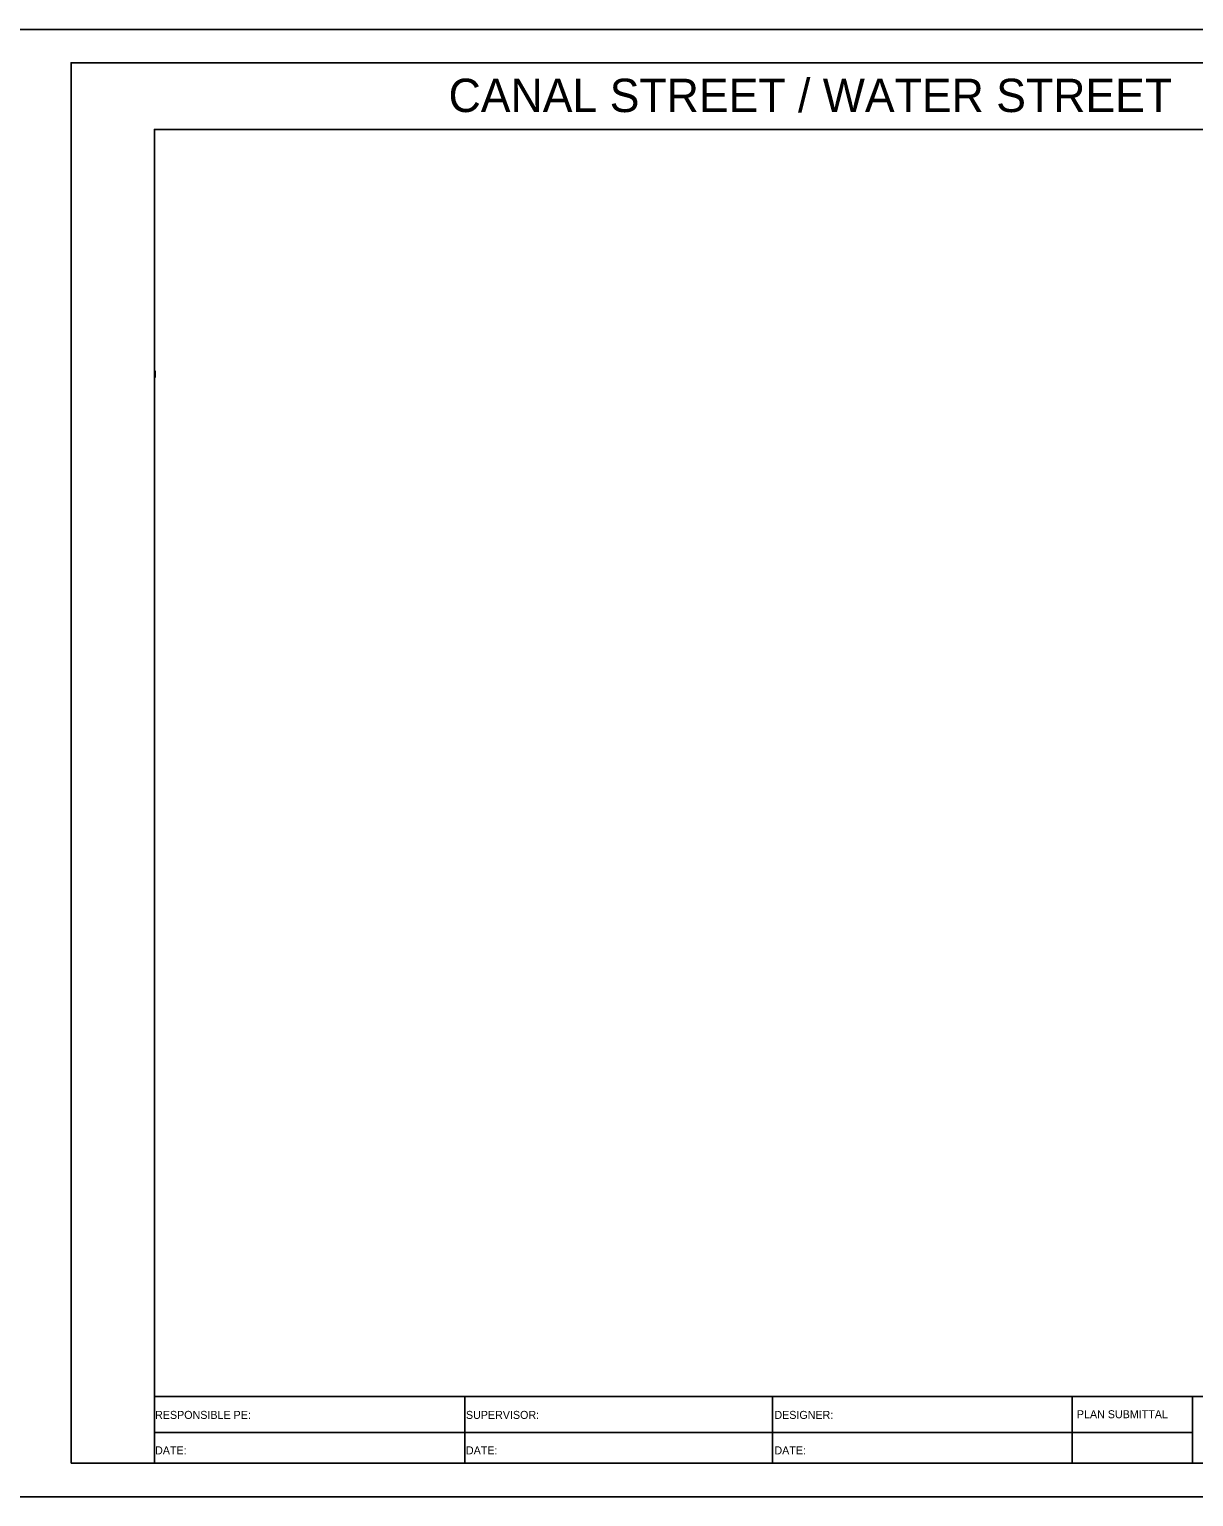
# Model space of a CAD drawing. Extents: x 1797478 to 1808916, y 246529 to 250952.
# Drawn here: x 1802802.3 to 1802976.8, y 250064.4 to 250284.4 of the extents above; entities that cross this region are included whole.
import ezdxf

# ---------------------------------------------------------------- set-up
doc = ezdxf.new("R2010")
doc.units = 0
for name, color, linetype in [('2', 7, 'Continuous'), ('ANNO-SHT', 7, 'Continuous'), ('ANNO-TXT', 7, 'Continuous'), ('AXIS', 7, 'Continuous'), ('DRAINAGE', 7, 'Continuous'), ('Level 1', 7, 'Continuous'), ('Level 62', 7, 'Continuous'), ('SHT-BDR', 7, 'Continuous'), ('SHT-BNDRY', 7, 'Continuous')]:
    doc.layers.add(name, color=color, linetype=linetype)

# ---------------------------------------------------------------- blocks, each defined once
blk = doc.blocks.new('SC47208')
at = {"layer": 'Level 1'}
blk.add_line((0, 0), (0, 0), dxfattribs=at)

msp = doc.modelspace()

# ---------------------------------------------------------------- linework, layer by layer
at = {"layer": '2'}
msp.add_lwpolyline([(1802821.12, 250233.21), (1802821.1, 250232.21)], dxfattribs=at)
msp.add_lwpolyline([(1802821.12, 250233.21), (1802821.1, 250232.21)], dxfattribs=at)
at = {"layer": 'AXIS'}
msp.add_line((1802821, 250189.42), (1802821, 250189.43), dxfattribs=at)
at = {"layer": 'Level 62'}
msp.add_lwpolyline([(1802796, 250064.42), (1803136, 250064.42), (1803136, 250284.42), (1802796, 250284.42)], close=True, dxfattribs=at)
at = {"layer": 'SHT-BDR'}
msp.add_lwpolyline([(1802821, 250079.43), (1803121, 250079.43), (1803121, 250269.43), (1802821, 250269.43)], close=True, dxfattribs=at)
at = {"layer": 'SHT-BNDRY'}
for p, q in [((1802821, 250069.42), (1802821, 250079.43)), ((1802867.52, 250079.43), (1802867.52, 250069.42)), ((1802913.67, 250069.42), (1802913.67, 250079.43)), ((1802958.59, 250069.42), (1802958.59, 250079.43)), ((1802976.63, 250069.42), (1802976.63, 250079.43)), ((1802821, 250074.03), (1802976.63, 250074.03))]:
    msp.add_line(p, q, dxfattribs=at)
msp.add_lwpolyline([(1802808.5, 250069.42), (1803131, 250069.42), (1803131, 250279.42), (1802808.5, 250279.42)], close=True, dxfattribs=at)

# ---------------------------------------------------------------- block references
at = {"layer": 'DRAINAGE', "xscale": 0.2, "yscale": 0.20000000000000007, "rotation": -116.41666666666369}
msp.add_blockref('SC47208', (1802971.32, 250274.62), dxfattribs=at)
msp.add_blockref('SC47208', (1802971.32, 250274.62), dxfattribs=at)

# ---------------------------------------------------------------- texts
at = {"layer": 'ANNO-SHT'}
msp.add_text('         CANAL STREET / WATER STREET         ', height=4.9995, rotation=360, dxfattribs=at).set_placement((1802848.38, 250272.02))
at = {"layer": 'ANNO-TXT'}
for s, p in [('RESPONSIBLE PE:', (1802821.1, 250076.08)), ('SUPERVISOR:', (1802867.7, 250076.08)), ('DESIGNER:', (1802913.94, 250076.08)), ('PLAN SUBMITTAL', (1802959.28, 250076.18)), ('DATE:', (1802821.1, 250070.76)), ('DATE:', (1802867.7, 250070.76)), ('DATE:', (1802913.94, 250070.76))]:
    msp.add_text(s, height=1.2, rotation=360, dxfattribs=at).set_placement(p)

doc.saveas('drawing.dxf')
